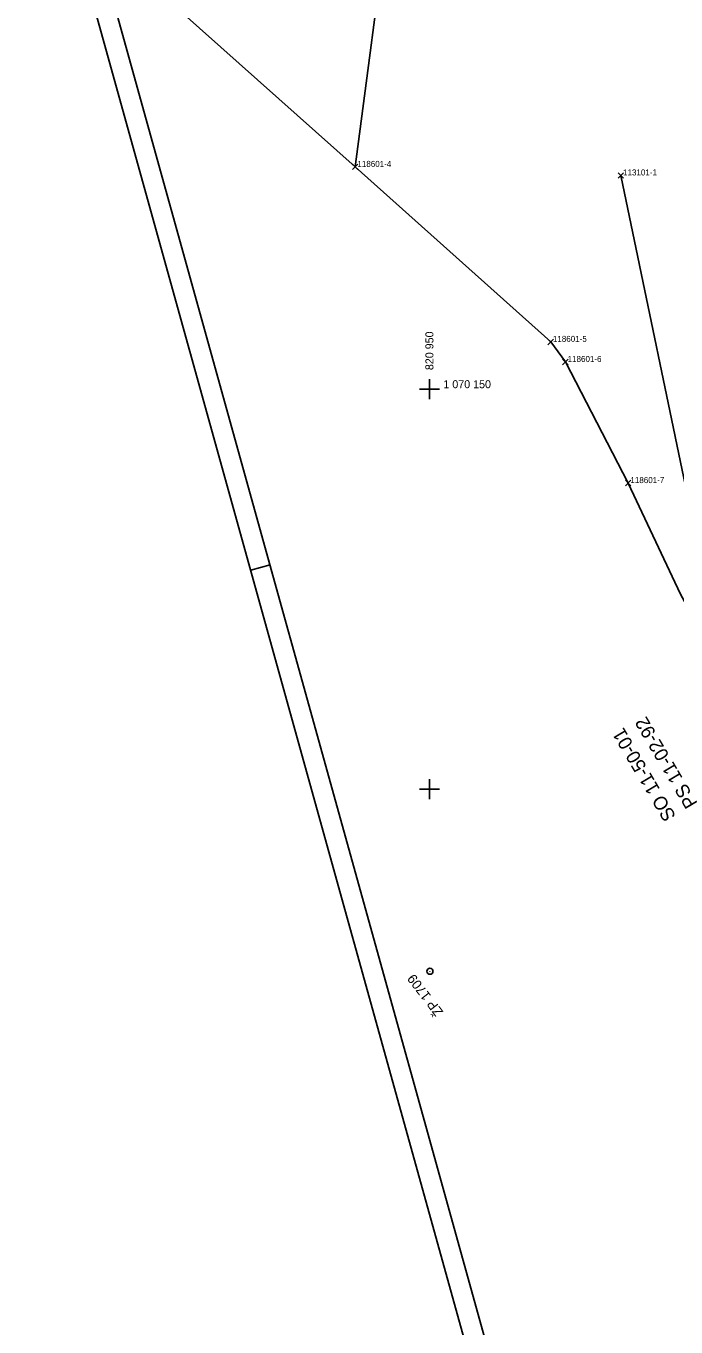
# Model space of a CAD drawing. Extents: x -821029 to -820632, y -1070881 to -1069931.
# Drawn here: x -821000.4 to -820919.2, y -1070267.2 to -1070104.6 of the extents above; entities that cross this region are included whole.
import ezdxf

# ---------------------------------------------------------------- set-up
doc = ezdxf.new("R2010")
doc.units = 0
for name, color, linetype in [('_PS_SO_číslo', 7, 'Continuous'), ('PS-11-02-31', 7, 'Continuous'), ('Ram', 7, 'Continuous'), ('Sit', 7, 'Continuous'), ('SO-11-31-01', 7, 'Continuous'), ('SO-11-86-01', 7, 'Continuous'), ('VB_SO-11-31-01', 7, 'Continuous'), ('VB_SO-11-86-01', 7, 'Continuous'), ('ZBP', 7, 'Continuous')]:
    doc.layers.add(name, color=color, linetype=linetype)

msp = doc.modelspace()

# ---------------------------------------------------------------- linework, layer by layer
at = {"layer": 'PS-11-02-31'}
for points in [[(-820987.51, -1070087.08), (-820988.29, -1070096.33), (-820959.28, -1070122.22)], [(-820959.28, -1070122.22), (-820934.84, -1070144.09), (-820933, -1070146.6), (-820925.15, -1070161.74), (-820918.63, -1070175.61), (-820911.37, -1070188.87), (-820902.58, -1070186.65), (-820896.69, -1070196.98), (-820870.46, -1070236.45), (-820846.57, -1070277.08), (-820842.6, -1070282.11), (-820813.47, -1070365.17), (-820809.8, -1070374.33), (-820792.8, -1070426.72), (-820792.34, -1070428.47), (-820790.08, -1070430.86), (-820788.92, -1070435.58), (-820780.39, -1070470.86), (-820770.55, -1070511.61), (-820767.89, -1070524.68), (-820765.3, -1070562.4), (-820759.61, -1070562.18)]]:
    msp.add_lwpolyline(points, dxfattribs=at)
at = {"layer": 'Ram'}
msp.add_line((-820969.91, -1070171.97), (-820972.32, -1070172.64), dxfattribs=at)
for points in [[(-820857.35, -1070031.72), (-820632.46, -1070841.06), (-820775.54, -1070880.81), (-821000.43, -1070071.48)], [(-820859.09, -1070034.8), (-820635.54, -1070839.32), (-820773.8, -1070877.73), (-820997.35, -1070073.22)]]:
    msp.add_lwpolyline(points, dxfattribs=at)
at = {"layer": 'Sit'}
for p, q in [((-820950, -1070148.75), (-820950, -1070150)), ((-820951.25, -1070150), (-820950, -1070150)), ((-820948.75, -1070150), (-820950, -1070150)), ((-820950, -1070151.25), (-820950, -1070150)), ((-820951.25, -1070200), (-820950, -1070200)), ((-820950, -1070198.75), (-820950, -1070200)), ((-820948.75, -1070200), (-820950, -1070200)), ((-820950, -1070201.25), (-820950, -1070200))]:
    msp.add_line(p, q, dxfattribs=at)
at = {"layer": 'SO-11-31-01'}
msp.add_lwpolyline([(-820926.07, -1070123.29), (-820916.95, -1070167.12), (-820908.61, -1070171.6), (-820902.99, -1070184.31), (-820895.92, -1070196.33), (-820868.5, -1070237.37), (-820845.66, -1070276.46), (-820841.66, -1070281.51), (-820839.82, -1070285.2), (-820808.13, -1070374.18), (-820790.33, -1070426.97), (-820782.93, -1070433.41), (-820769.19, -1070488.5), (-820779.76, -1070491.37)], dxfattribs=at)
at = {"layer": 'SO-11-86-01'}
msp.add_lwpolyline([(-820955.09, -1070090.19), (-820959.28, -1070122.22), (-820934.84, -1070144.09), (-820933, -1070146.6), (-820925.15, -1070161.74), (-820918.63, -1070175.61), (-820911.37, -1070188.87), (-820902.58, -1070186.65), (-820896.69, -1070196.98), (-820870.46, -1070236.45), (-820846.57, -1070277.08)], dxfattribs=at)
at = {"layer": 'VB_SO-11-31-01'}
for p, q in [((-820926.41, -1070123.63), (-820925.73, -1070122.95)), ((-820925.73, -1070123.63), (-820926.41, -1070122.95))]:
    msp.add_line(p, q, dxfattribs=at)
at = {"layer": 'VB_SO-11-86-01'}
for p, q in [((-820959.62, -1070122.56), (-820958.93, -1070121.87)), ((-820958.93, -1070122.56), (-820959.62, -1070121.87)), ((-820935.18, -1070144.44), (-820934.5, -1070143.75)), ((-820934.5, -1070144.44), (-820935.18, -1070143.75)), ((-820933.35, -1070146.95), (-820932.66, -1070146.26)), ((-820932.66, -1070146.95), (-820933.35, -1070146.26)), ((-820925.49, -1070162.08), (-820924.8, -1070161.39)), ((-820924.8, -1070162.08), (-820925.49, -1070161.39))]:
    msp.add_line(p, q, dxfattribs=at)
at = {"layer": 'ZBP'}
msp.add_line((-820949.94, -1070222.78), (-820949.95, -1070222.73), dxfattribs=at)
msp.add_circle((-820949.94, -1070222.75), 0.378, dxfattribs=at)

# ---------------------------------------------------------------- texts
at = {"layer": '_PS_SO_číslo'}
for s, p in [('PS 11-02-92', (-820916.42, -1070201.76)), ('SO 11-50-01', (-820919.13, -1070203.37))]:
    msp.add_text(s, height=1.7, rotation=120.6328, dxfattribs=at).set_placement(p)
at = {"layer": 'Sit'}
msp.add_text('820 950', height=1, rotation=90, dxfattribs=at).set_placement((-820949.5, -1070147.62))
msp.add_text('1 070 150', height=1, dxfattribs=at).set_placement((-820948.25, -1070149.88))
at = {"layer": 'VB_SO-11-31-01'}
msp.add_text(' 113101-1', height=0.75, dxfattribs=at).set_placement((-820926.07, -1070123.29))
at = {"layer": 'VB_SO-11-86-01'}
for s, p in [(' 118601-4', (-820959.28, -1070122.22)), (' 118601-5', (-820934.84, -1070144.09)), (' 118601-6', (-820933, -1070146.6)), (' 118601-7', (-820925.15, -1070161.74))]:
    msp.add_text(s, height=0.75, dxfattribs=at).set_placement(p)
at = {"layer": 'ZBP'}
msp.add_text('ŽP 1709', height=1.2, rotation=127.376, dxfattribs=at).set_placement((-820948.22, -1070227.8))

doc.saveas('drawing.dxf')
